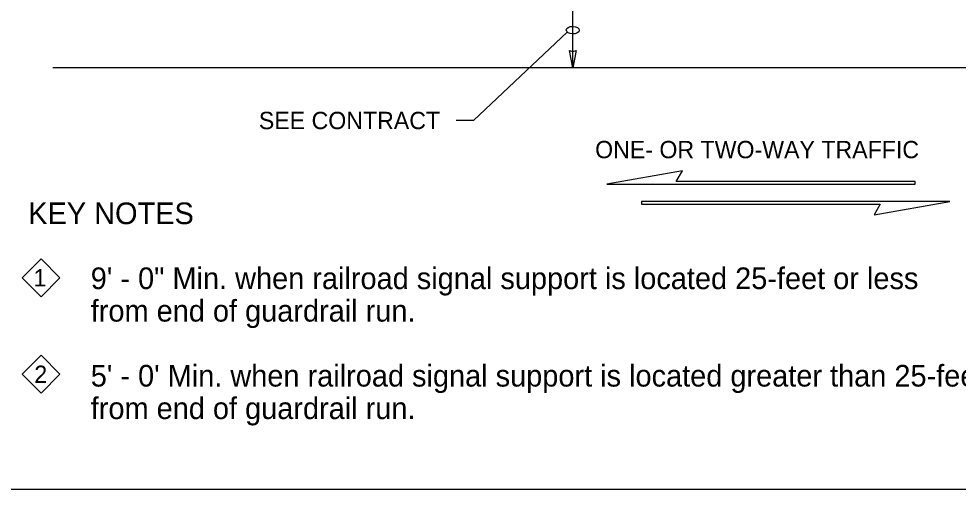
# Model space of a CAD drawing. Extents: x 99862 to 103680, y 99470 to 102076.
# Drawn here: x 100301 to 101170, y 100000 to 100434 of the extents above; entities that cross this region are included whole.
import ezdxf

# ---------------------------------------------------------------- set-up
doc = ezdxf.new("R2010")
doc.units = 0
for name, color, linetype in [('Level 1', 7, 'Continuous'), ('Level 11', 7, 'Continuous'), ('Level 15', 7, 'Continuous'), ('Level 20', 7, 'Continuous'), ('Level 3', 7, 'Continuous')]:
    doc.layers.add(name, color=color, linetype=linetype)

msp = doc.modelspace()

# ---------------------------------------------------------------- linework, layer by layer
at = {"layer": 'Level 1'}
msp.add_lwpolyline([(99862, 99999.5), (103151, 99999.5), (103151, 102075.5), (99862, 102075.5)], close=True, dxfattribs=at)
at = {"layer": 'Level 11'}
msp.add_line((100332.36, 100388.97), (102370.95, 100388.97), dxfattribs=at)
at = {"layer": 'Level 15'}
for p, q in [((100813.08, 100388.97), (100813.08, 100460.97)), ((100807.96, 100421.73), (100721.23, 100340.01)), ((100721.23, 100340.01), (100705.23, 100340.01))]:
    msp.add_line(p, q, dxfattribs=at)
msp.add_lwpolyline([(100813.08, 100388.79), (100809.99, 100404.52), (100813.08, 100403.79), (100816.16, 100404.52)], close=True, dxfattribs=at)
msp.add_ellipse((100813.08, 100423.45), major_axis=(-6, 0.16), ratio=0.57735, dxfattribs=at)
at = {"layer": 'Level 20'}
for points in [[(100321.38, 100212.27), (100338.93, 100194.72), (100321.38, 100177.16), (100303.83, 100194.72)], [(100321.38, 100123.17), (100338.93, 100105.62), (100321.38, 100088.07), (100303.83, 100105.62)]]:
    msp.add_lwpolyline(points, close=True, dxfattribs=at)
at = {"layer": 'Level 3'}
for points in [[(101129.58, 100283.63), (100908.85, 100283.63), (100914.55, 100293.49), (100844.58, 100281.15), (101129.58, 100281.15)], [(100876.71, 100262.68), (101097.45, 100262.68), (101091.75, 100252.82), (101161.72, 100265.15), (100876.71, 100265.15)]]:
    msp.add_lwpolyline(points, close=True, dxfattribs=at)

# ---------------------------------------------------------------- texts
at = {"layer": 'Level 20'}
for s, height, p in [('SEE CONTRACT', 16, (100522.81, 100332.01)), ('ONE- OR TWO-WAY TRAFFIC', 16, (100833.78, 100305.16)), ('KEY NOTES', 20, (100309.58, 100244.28)), ('1', 16, (100314.43, 100186.72)), ('9\' - 0" Min. when railroad signal support is located 25-feet or less', 20, (100367.38, 100184.28)), ('from end of guardrail run.', 20, (100367.38, 100154.28)), ('2', 16, (100315.2, 100097.62)), ("5' - 0' Min. when railroad signal support is located greater than 25-feet", 20, (100367.38, 100094.28)), ('from end of guardrail run.', 20, (100367.38, 100064.28))]:
    msp.add_text(s, height=height, dxfattribs=at).set_placement(p)

doc.saveas('drawing.dxf')
